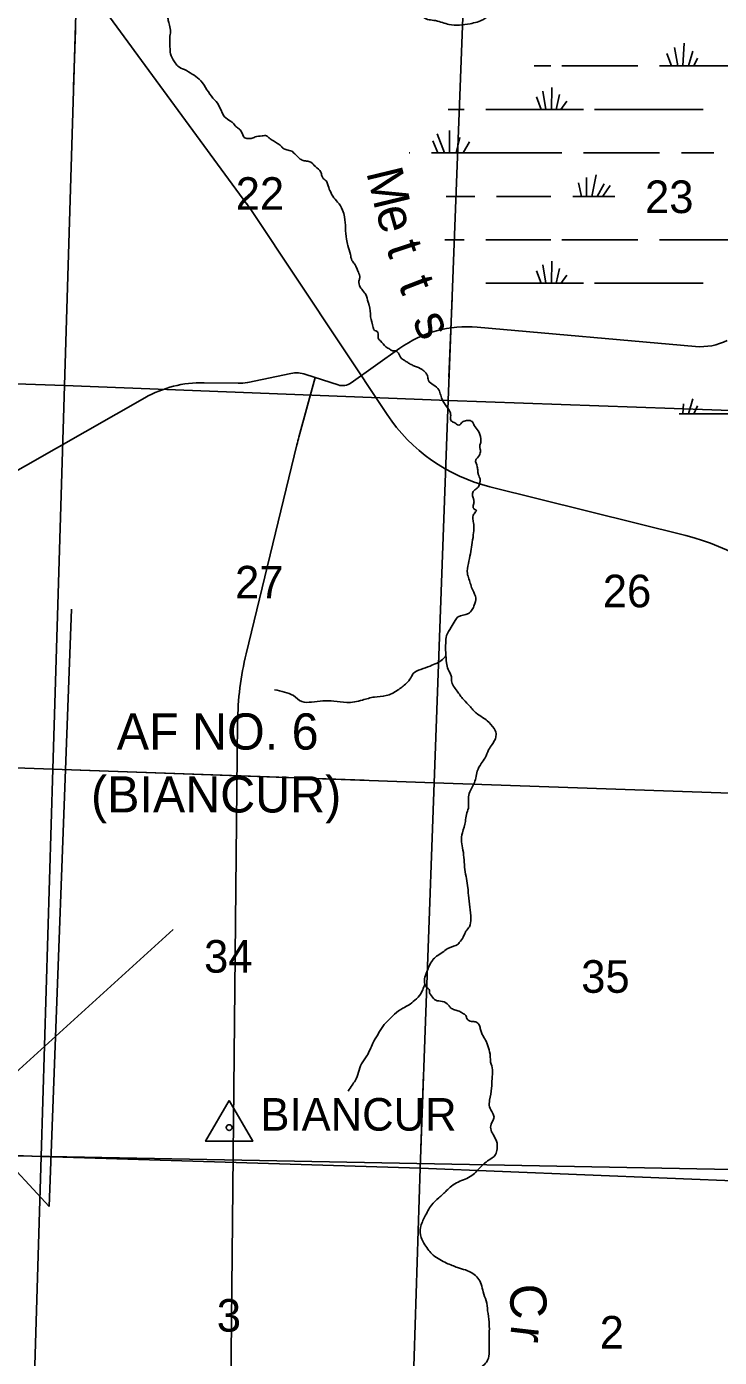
# Model space of a CAD drawing. Extents: x 1219626 to 1426462, y 456797 to 752399.
# Drawn here: x 1262506 to 1272069, y 595218 to 613588 of the extents above; entities that cross this region are included whole.
import ezdxf

# ---------------------------------------------------------------- set-up
doc = ezdxf.new("R2010")
doc.units = 0
for name, color, linetype in [('Airport Names', 7, 'Continuous'), ('Lakes and Ponds', 7, 'Continuous'), ('Masks', 7, 'Continuous'), ('Narrow River Creek and Branch and Slough', 7, 'Continuous'), ('Narrow River Creek and Branch and Slough Text', 7, 'Continuous'), ('Quad Borders', 7, 'Continuous'), ('Runways', 7, 'Continuous'), ('Section Lines', 7, 'Continuous'), ('Section Numbers', 7, 'Continuous'), ('Swamps', 7, 'Continuous'), ('Triangulation Station', 7, 'Continuous'), ('Triangulation Station Text', 7, 'Continuous'), ('Uninventoried Roads and Features', 7, 'Continuous')]:
    doc.layers.add(name, color=color, linetype=linetype)

msp = doc.modelspace()

# ---------------------------------------------------------------- linework, layer by layer
at = {"layer": 'Lakes and Ponds'}
for points in [[(1259354, 612674), (1259278, 612860), (1259217, 613159), (1259222, 613302), (1259294, 613478), (1259450, 613617), (1259637, 613629), (1259747, 613578), (1259915, 613502), (1260060, 613471), (1260171, 613452), (1260266, 613460), (1260274, 613559), (1260072, 613640), (1259980, 613708), (1259934, 613891), (1259960, 614112), (1260049, 614209), (1260110, 614246), (1260177, 614297), (1260249, 614361), (1260338, 614506), (1260434, 614699), (1260442, 614859), (1260506, 615052), (1260650, 615196), (1260747, 615229), (1260843, 615188), (1260883, 615060), (1260921, 614935), (1260978, 614801), (1261039, 614721), (1261111, 614687), (1261298, 614740), (1261470, 614866), (1261630, 615027), (1261758, 615253), (1261852, 615447), (1262008, 615561), (1262023, 615598), (1262087, 615678), (1262207, 615718), (1262360, 615726), (1262498, 615729), (1262620, 615760), (1262721, 615774), (1262841, 615718), (1262970, 615622), (1263178, 615542), (1263355, 615445), (1263483, 615357), (1263628, 615253), (1263660, 615148), (1263677, 615042), (1263708, 615023), (1263796, 615004), (1263868, 615065), (1263949, 615245), (1264086, 615374), (1264273, 615401), (1264398, 615389), (1264623, 615341), (1264767, 615333), (1264879, 615413), (1265024, 615534), (1265208, 615662), (1265345, 615710), (1265481, 615702), (1265658, 615670), (1265708, 615664), (1266006, 615676), (1266084, 615638), (1266322, 615515), (1266494, 615431), (1266731, 615359), (1266814, 615245), (1266918, 615111), (1267044, 615015), (1267159, 614980), (1267264, 615012), (1267432, 615084), (1267609, 615132), (1267882, 615116), (1267994, 615124), (1268170, 615092), (1268251, 615004), (1268162, 614980), (1268089, 615004), (1268020, 615034), (1267933, 614992), (1267721, 614996)], [(1269182, 614025), (1269105, 613880), (1268991, 613819), (1268812, 613688), (1268628, 613628), (1268338, 613617), (1268151, 613670), (1267987, 613716), (1267919, 613830), (1267761, 613921), (1267650, 614034), (1267624, 614305), (1267448, 614420), (1267425, 614458), (1267391, 614611), (1267353, 614656), (1266979, 614809), (1266784, 614901), (1266750, 614924), (1266654, 615084), (1266628, 615187), (1266353, 615286), (1266231, 615366), (1266100, 615447), (1265907, 615455), (1265763, 615455), (1265719, 615462), (1265514, 615527), (1265354, 615471), (1265298, 615447), (1265048, 615278), (1264936, 615174), (1264767, 615101), (1264597, 615099), (1264501, 615141), (1264425, 615218), (1264196, 615195), (1264117, 615085), (1264029, 614941), (1263900, 614844), (1263764, 614764), (1263604, 614772), (1263531, 614917), (1263515, 615045), (1263419, 615182), (1263218, 615334), (1262954, 615487), (1262809, 615559), (1262584, 615591), (1262432, 615567), (1262312, 615495), (1262183, 615382), (1262063, 615302), (1261983, 615214), (1261898, 615088), (1261838, 614901), (1261750, 614772), (1261581, 614628), (1261429, 614547), (1261300, 614507), (1261211, 614488), (1261077, 614473), (1260940, 614496), (1260837, 614576), (1260783, 614668), (1260779, 614852), (1260779, 614882), (1260739, 614973), (1260683, 614917), (1260675, 614836), (1260667, 614724), (1260650, 614571), (1260636, 614524), (1260587, 614436), (1260480, 614322), (1260320, 614150), (1260220, 613955), (1260278, 613818), (1260472, 613701), (1260554, 613455), (1260488, 613362), (1260224, 613239), (1260106, 613255), (1259864, 613335), (1259688, 613423), (1259511, 613383), (1259455, 613247), (1259471, 613030), (1259535, 612813), (1259579, 612575), (1259559, 612412)]]:
    msp.add_spline(points, degree=3, dxfattribs=at)
at = {"layer": 'Masks'}
for p, q in [((1263180, 613545), (1263155, 612755)), ((1268378, 609843), (1268336, 608749)), ((1263245, 603326), (1267164, 603184)), ((1267986, 599124), (1267949, 598108))]:
    msp.add_line(p, q, dxfattribs=at)
at = {"layer": 'Narrow River Creek and Branch and Slough'}
for points in [[(1266192, 611847), (1266165, 611867), (1266097, 611888), (1266046, 611909), (1266015, 611942), (1265968, 611976), (1265913, 612010), (1265852, 612051), (1265818, 612079), (1265756, 612079), (1265661, 612065), (1265607, 612044), (1265573, 612044), (1265518, 612051), (1265491, 612092), (1265464, 612147), (1265443, 612174), (1265395, 612208), (1265355, 612256), (1265320, 612283), (1265239, 612344), (1265205, 612399), (1265139, 612530), (1265058, 612626), (1264887, 612864), (1264792, 612933), (1264683, 612994), (1264594, 613042), (1264547, 613103), (1264492, 613212), (1264485, 613307), (1264485, 613457), (1264492, 613539), (1264472, 613628), (1264458, 613689), (1264458, 613751), (1264472, 613839), (1264451, 613907), (1264404, 613982), (1264342, 614057), (1264288, 614098), (1264206, 614125), (1264124, 614132), (1264097, 614153), (1264070, 614207), (1264042, 614269), (1263968, 614303), (1263913, 614344), (1263865, 614446), (1263852, 614514), (1263811, 614589), (1263763, 614630), (1263743, 614657), (1263702, 614745)], [(1268693, 606878), (1268713, 606912), (1268686, 606926), (1268672, 606946), (1268679, 607007), (1268679, 607055), (1268665, 607096), (1268665, 607157), (1268706, 607205), (1268740, 607232), (1268761, 607287), (1268767, 607334), (1268754, 607375), (1268740, 607409), (1268733, 607457), (1268727, 607512), (1268706, 607607), (1268740, 607648), (1268767, 607703), (1268767, 607757), (1268761, 607798), (1268774, 607846), (1268774, 607900), (1268740, 608009), (1268686, 608084), (1268665, 608125), (1268618, 608152), (1268563, 608146), (1268509, 608118), (1268488, 608091), (1268454, 608091), (1268406, 608125), (1268366, 608146), (1268359, 608200), (1268352, 608268), (1268284, 608371), (1268222, 608500), (1268195, 608575), (1268120, 608643), (1268052, 608705), (1268039, 608766), (1268011, 608814), (1267964, 608855), (1267861, 608902), (1267814, 608923), (1267766, 608950), (1267718, 608984), (1267677, 609011), (1267637, 609080), (1267609, 609107), (1267555, 609114), (1267521, 609134), (1267466, 609168), (1267391, 609250), (1267364, 609277), (1267357, 609311), (1267357, 609345), (1267344, 609379), (1267310, 609393), (1267289, 609434), (1267255, 609584), (1267235, 609741), (1267221, 609782), (1267187, 609891), (1267153, 609938), (1267112, 609993), (1267092, 610075), (1267105, 610122), (1267085, 610197), (1267064, 610252), (1267030, 610313), (1266996, 610361), (1266976, 610443), (1266942, 610565), (1266921, 610654), (1266894, 610961), (1266867, 611056), (1266799, 611165), (1266731, 611247), (1266703, 611302), (1266669, 611390), (1266649, 611445), (1266601, 611492), (1266581, 611526), (1266567, 611581), (1266492, 611656), (1266431, 611717), (1266370, 611731), (1266308, 611745), (1266261, 611779), (1266192, 611847)], [(1268911, 599295), (1268897, 599438), (1268863, 599547), (1268842, 599595), (1268795, 599677), (1268774, 599731), (1268761, 599786), (1268733, 599833), (1268679, 599854), (1268645, 599854), (1268584, 599895), (1268570, 599936), (1268522, 599970), (1268475, 599997), (1268413, 600017), (1268359, 600045), (1268331, 600079), (1268243, 600133), (1268154, 600147), (1268093, 600208), (1268066, 600263), (1268066, 600283), (1268025, 600331), (1268004, 600372), (1268004, 600467), (1268039, 600563), (1268073, 600638), (1268120, 600713), (1268182, 600767), (1268263, 600822), (1268331, 600869), (1268461, 600924), (1268495, 600965), (1268543, 601040), (1268570, 601101), (1268618, 601163), (1268638, 601272), (1268624, 601435), (1268604, 601599), (1268597, 601701), (1268556, 601953), (1268529, 602221), (1268509, 602337), (1268522, 602460), (1268563, 602616), (1268577, 602712), (1268604, 602800), (1268604, 602930), (1268624, 603025), (1268679, 603134), (1268706, 603216), (1268727, 603312), (1268781, 603414), (1268836, 603496), (1268883, 603605), (1268931, 603680), (1268965, 603734), (1268985, 603795), (1268979, 603864), (1268958, 603898), (1268863, 604007), (1268727, 604102), (1268679, 604143), (1268631, 604198), (1268536, 604300), (1268447, 604416), (1268372, 604559), (1268366, 604627), (1268325, 604716), (1268304, 604804), (1268291, 604947), (1268291, 605078), (1268304, 605181), (1268366, 605296), (1268420, 605392), (1268461, 605440), (1268604, 605487), (1268658, 605542), (1268686, 605603), (1268706, 605699), (1268665, 605808), (1268611, 605964), (1268590, 606039), (1268604, 606176), (1268631, 606312), (1268652, 606435), (1268672, 606571), (1268679, 606680), (1268672, 606755), (1268665, 606823), (1268693, 606878)], [(1265929, 604435), (1266066, 604401), (1266188, 604353), (1266304, 604271), (1266440, 604265), (1266747, 604278), (1266924, 604258), (1267142, 604292), (1267306, 604333), (1267469, 604353), (1267626, 604428), (1267748, 604524), (1267810, 604599), (1267844, 604660), (1267946, 604714), (1268075, 604762), (1268171, 604803), (1268246, 604851), (1268293, 604905)], [(1266944, 598895), (1266999, 598977), (1267040, 599038), (1267088, 599154), (1267128, 599270), (1267203, 599379), (1267285, 599556), (1267353, 599672), (1267421, 599788), (1267510, 599883), (1267585, 599958), (1267701, 600040), (1267776, 600081), (1267864, 600149), (1267946, 600238), (1267973, 600292), (1268004, 600373)], [(1267603, 588732), (1267596, 588957), (1267650, 589086), (1267691, 589195), (1267712, 589338), (1267718, 589447), (1267746, 589515), (1267746, 589652), (1267725, 589720), (1267664, 589761), (1267596, 589809), (1267555, 589856), (1267487, 589972), (1267487, 590068), (1267528, 590211), (1267555, 590286), (1267609, 590381), (1267684, 590470), (1267718, 590531), (1267752, 590674), (1267773, 590831), (1267800, 591001), (1267807, 591138), (1267821, 591315), (1267793, 591478), (1267732, 591628), (1267698, 591806), (1267657, 591901), (1267630, 592044), (1267589, 592296), (1267575, 592419), (1267541, 592562), (1267533, 592788), (1267548, 592829), (1267559, 592917), (1267559, 593174), (1267602, 593325), (1267616, 593536), (1267643, 593627), (1267691, 593736), (1267841, 593845), (1267930, 593872), (1268092, 593894), (1268236, 593947), (1268359, 594056), (1268447, 594172), (1268468, 594322), (1268529, 594635), (1268570, 594806), (1268624, 594894), (1268733, 595037), (1268829, 595126), (1268870, 595181), (1268890, 595296), (1268890, 595460), (1268890, 595705), (1268870, 595862), (1268849, 595999), (1268808, 596121), (1268781, 596230), (1268665, 596377), (1268454, 596459), (1268304, 596520), (1268209, 596568), (1268120, 596629), (1268004, 596772), (1267950, 596875), (1267943, 597011), (1268004, 597161), (1268093, 597318), (1268195, 597420), (1268304, 597522), (1268372, 597584), (1268461, 597638), (1268652, 597727), (1268788, 597863), (1268870, 597931), (1268979, 598020), (1268999, 598095), (1268999, 598177), (1268958, 598273), (1268917, 598354), (1268917, 598436), (1268958, 598532), (1268938, 598593), (1268897, 598675), (1268897, 598770), (1268924, 598934), (1268931, 599063), (1268938, 599186), (1268911, 599295)], [(1263759, 588864), (1263706, 588988), (1263641, 589070), (1263577, 589123), (1263524, 589200), (1263500, 589276), (1263524, 589376), (1263536, 589529), (1263541, 589665), (1263536, 589770), (1263512, 589900), (1263512, 590006), (1263500, 590100), (1263459, 590247), (1263418, 590365), (1263347, 590500), (1263283, 590588), (1263200, 590682), (1263136, 590729), (1263071, 590770), (1263006, 590835), (1262942, 590900), (1262848, 590982), (1262777, 591035), (1262683, 591106), (1262595, 591188), (1262554, 591241), (1262460, 591288), (1262413, 591318), (1262342, 591400), (1262272, 591523), (1262225, 591629), (1262101, 591812), (1262054, 591871), (1261913, 591994), (1261772, 592129), (1261678, 592235), (1261587, 592359), (1261522, 592418), (1261428, 592547), (1261322, 592641), (1261216, 592777), (1261040, 592947), (1260799, 593200), (1260687, 593294), (1260522, 593447), (1260364, 593624), (1260234, 593788), (1260134, 593888), (1259952, 594030), (1259829, 594136), (1259782, 594194), (1259729, 594236), (1259664, 594294), (1259605, 594359), (1259523, 594424), (1259417, 594500), (1259288, 594612), (1259200, 594706), (1259111, 594788), (1258982, 594888), (1258800, 595000), (1258570, 595141), (1258359, 595283), (1258212, 595394), (1258059, 595494), (1257935, 595594), (1257783, 595753), (1257577, 595950), (1257412, 596097), (1257277, 596226), (1257230, 596297), (1257224, 596379), (1257271, 596438), (1257377, 596562), (1257447, 596650), (1257500, 596738), (1257489, 596826), (1257536, 596932), (1257577, 596985), (1257606, 597068), (1257641, 597168), (1257659, 597232), (1257653, 597297), (1257636, 597332), (1257583, 597362), (1257477, 597421), (1257424, 597462), (1257348, 597532), (1257236, 597679), (1257148, 597797)]]:
    msp.add_spline(points, degree=3, dxfattribs=at)
at = {"layer": 'Quad Borders'}
msp.add_line((1260831, 598030), (1300143, 597276), dxfattribs=at)
at = {"layer": 'Runways'}
for p, q in [((1263126, 605545), (1262817, 597303)), ((1261677, 598537), (1264528, 601124)), ((1259530, 600852), (1262817, 597303))]:
    msp.add_line(p, q, dxfattribs=at)
at = {"layer": 'Section Lines'}
for p, q in [((1263191, 613912), (1263029, 608636)), ((1268324, 608428), (1268525, 613717)), ((1257686, 608801), (1263029, 608636)), ((1263029, 608636), (1262868, 603340)), ((1263029, 608636), (1268324, 608428)), ((1268132, 603148), (1268324, 608428)), ((1268324, 608428), (1273556, 608243)), ((1262868, 603340), (1257528, 603509)), ((1262868, 603340), (1262705, 597993)), ((1268132, 603148), (1262868, 603340)), ((1267939, 597831), (1268132, 603148)), ((1273394, 602966), (1268132, 603148)), ((1262705, 597993), (1257356, 598196)), ((1262705, 597993), (1262553, 592949)), ((1267939, 597831), (1262705, 597993)), ((1267773, 592760), (1267939, 597831)), ((1273213, 597617), (1267939, 597831))]:
    msp.add_line(p, q, dxfattribs=at)
at = {"layer": 'Swamps'}
for p, q in [((1271565, 613045), (1271582, 613361)), ((1271409, 613045), (1271344, 613217)), ((1271494, 613045), (1271448, 613299)), ((1271642, 613045), (1271700, 613249)), ((1269894, 613045), (1270944, 613045)), ((1271244, 613045), (1272294, 613045)), ((1271718, 613045), (1271767, 613154)), ((1269672, 612445), (1269632, 612698)), ((1269750, 612445), (1269755, 612749)), ((1269817, 612445), (1269860, 612651)), ((1268844, 612445), (1269444, 612445)), ((1269444, 612445), (1270194, 612445)), ((1269609, 612446), (1269543, 612619)), ((1269879, 612444), (1269963, 612558)), ((1270344, 612445), (1271844, 612445)), ((1268173, 612108), (1268276, 611845)), ((1268342, 612156), (1268342, 611845)), ((1268113, 612011), (1268184, 611845)), ((1268487, 612059), (1268434, 611845)), ((1268620, 611999), (1268530, 611845)), ((1268094, 611845), (1269444, 611845)), ((1269444, 611845), (1269894, 611845)), ((1270194, 611845), (1271244, 611845)), ((1271544, 611845), (1271994, 611845)), ((1270367, 611540), (1270309, 611245)), ((1270126, 611431), (1270163, 611245)), ((1270235, 611504), (1270235, 611245)), ((1270476, 611419), (1270382, 611244)), ((1270561, 611395), (1270461, 611246)), ((1268994, 611245), (1269444, 611245)), ((1269444, 611245), (1269744, 611245)), ((1270044, 611245), (1270624, 611245)), ((1268844, 610645), (1269444, 610645)), ((1269444, 610645), (1269744, 610645)), ((1269894, 610645), (1270944, 610645)), ((1271244, 610645), (1272294, 610645)), ((1269672, 610045), (1269632, 610298)), ((1269750, 610045), (1269755, 610349)), ((1269817, 610045), (1269860, 610251)), ((1269609, 610046), (1269543, 610219)), ((1269879, 610044), (1269963, 610158)), ((1268844, 610045), (1269444, 610045)), ((1269444, 610045), (1270194, 610045)), ((1270344, 610045), (1271844, 610045)), ((1271642, 608245), (1271700, 608449)), ((1271718, 608245), (1271767, 608354))]:
    msp.add_line(p, q, dxfattribs=at)
for points in [[(1269511, 613045), (1269744, 613045)], [(1268326, 612445), (1268544, 612445)], [(1267788, 611845), (1267794, 611845)], [(1268298, 611245), (1268694, 611245)], [(1268281, 610645), (1268544, 610645)], [(1271515, 608245), (1272294, 608245)], [(1271565, 608245), (1271572, 608380)]]:
    msp.add_lwpolyline(points, dxfattribs=at)
at = {"layer": 'Triangulation Station'}
msp.add_lwpolyline([(1265302, 598765), (1264977, 598202), (1265627, 598202)], close=True, dxfattribs=at)
msp.add_circle((1265302, 598390), 40, dxfattribs=at)
at = {"layer": 'Uninventoried Roads and Features'}
for p, q in [((1265545, 611139), (1262568, 615199)), ((1267481, 608235), (1265618, 611035)), ((1271740, 609172), (1268726, 609439)), ((1267656, 609148), (1266984, 608669)), ((1266154, 608800), (1265558, 608677)), ((1266806, 608642), (1266359, 608788)), ((1265426, 608665), (1264955, 608673)), ((1266265, 607923), (1266489, 608746)), ((1264138, 608464), (1259334, 605731)), ((1265537, 604932), (1266237, 607813)), ((1271604, 606563), (1268899, 607236)), ((1265315, 593980), (1265418, 603983))]:
    msp.add_line(p, q, dxfattribs=at)
for centre, radius, start, end in [((1263287, 609484), 2800, 33.6378, 36.2471), ((1268585, 607845), 1600, 84.9387, 125.5021), ((1271810, 609969), 800, 264.9387, 297.0985), ((1266235, 608408), 400, 71.8429, 101.652), ((1264929, 607073), 1600, 89.0476, 119.6332), ((1265436, 609265), 600, 269.0476, 281.652), ((1266868, 608832), 200, 251.8429, 305.5021), ((1269479, 609565), 2400, 213.6378, 256.0299), ((1270318, 606821), 4200, 164.7821, 166.3392), ((1270832, 603457), 3200, 42.0023, 76.0299), ((1269618, 603940), 4200, 166.3392, 179.4083)]:
    msp.add_arc(centre, radius, start, end, dxfattribs=at)

# ---------------------------------------------------------------- texts
at = {"layer": 'Airport Names'}
for s, p in [('AF NO. 6', (1263750, 603608)), ('(BIANCUR)', (1263395, 602740))]:
    msp.add_text(s, height=500, dxfattribs=at).set_placement(p)
at = {"layer": 'Narrow River Creek and Branch and Slough Text'}
for s, rotation, p in [('M', 283.6172, (1267192, 611578)), ('e', 285.9083, (1267318, 611057)), ('t', 288.3531, (1267464, 610542)), ('t', 290.9578, (1267632, 610034)), ('s', 293.7268, (1267824, 609534)), ('C', 274.9122, (1269161, 596212)), ('r', 263.3727, (1269200, 595677))]:
    msp.add_text(s, height=500, rotation=rotation, dxfattribs=at).set_placement(p)
at = {"layer": 'Section Numbers'}
for s, rotation, p in [('22', 0, (1265392, 611059)), ('23', 0, (1271042, 611014)), ('27', 0.0001, (1265383, 605694)), ('26', 0.0001, (1270459, 605572)), ('34', 0.0001, (1264955, 600529)), ('35', 0.0001, (1270161, 600251)), ('3', 0.0001, (1265131, 595573)), ('2', 0.0001, (1270416, 595340))]:
    msp.add_text(s, height=450, rotation=rotation, dxfattribs=at).set_placement(p)
at = {"layer": 'Triangulation Station Text'}
msp.add_text('BIANCUR', height=450, rotation=0.0001, dxfattribs=at).set_placement((1265733, 598348))

doc.saveas('drawing.dxf')
